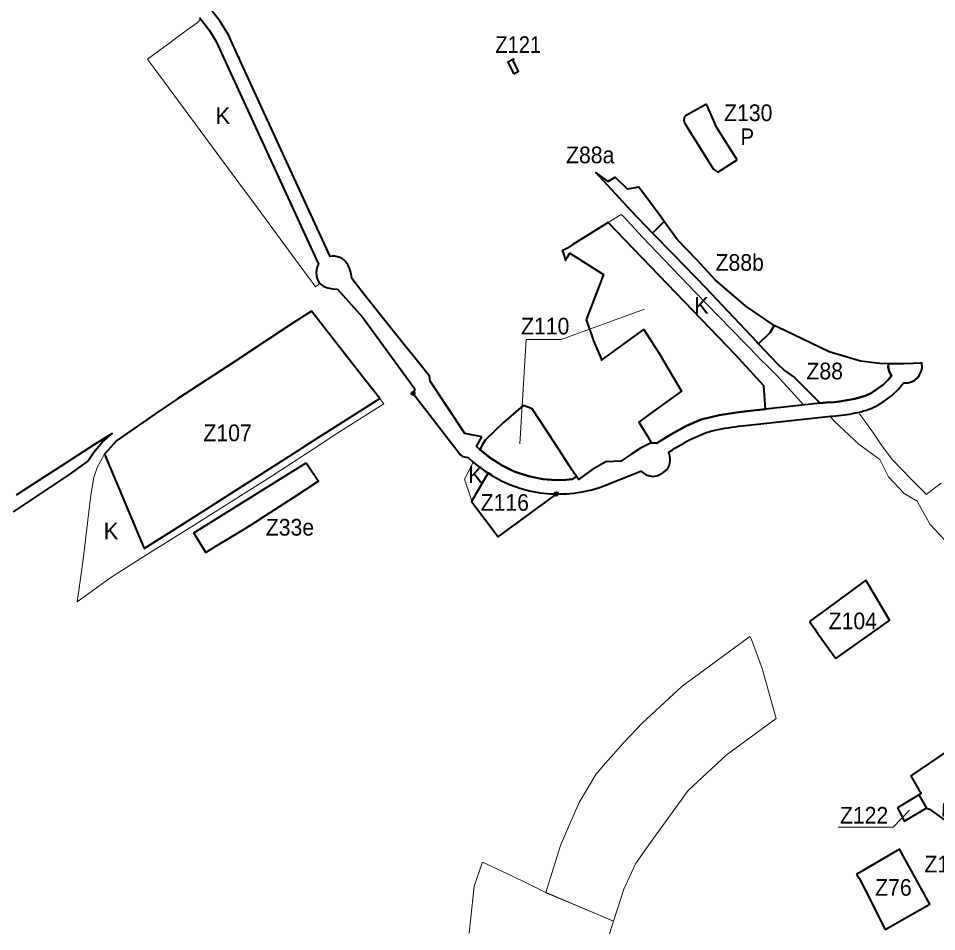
# Model space of a CAD drawing. Extents: x -650276 to -642489, y -1074311 to -1066658.
# Drawn here: x -648043 to -646722, y -1072934 to -1071620 of the extents above; entities that cross this region are included whole.
import ezdxf

# ---------------------------------------------------------------- set-up
doc = ezdxf.new("R2010")
doc.units = 0
doc.header["$LTSCALE"] = 9.6
doc.header["$PDMODE"] = 32
doc.header["$PDSIZE"] = 4.8
for name, color, linetype, lineweight in [('44', 7, 'Continuous', 40), ('45', 7, 'Continuous', 40), ('46', 7, 'Continuous', 13), ('47', 7, 'Continuous', 13), ('48', 7, 'Continuous', 13), ('60', 7, 'Continuous', 35)]:
    doc.layers.add(name, color=color, linetype=linetype, lineweight=lineweight)

msp = doc.modelspace()

# ---------------------------------------------------------------- linework, layer by layer
at = {"layer": '44'}
msp.add_line((-646978.602, -1072088.66), (-646951.95, -1072116.84), dxfattribs=at)
for points in [[(-647725.629, -1071678.373), (-647735.352, -1071657.117), (-647741.34, -1071644.028), (-647753.065, -1071625.201), (-647767.784, -1071606.225), (-647782.408, -1071590.847), (-647798.911, -1071576.526), (-647817.375, -1071563.458), (-647834.953, -1071553.406)], [(-647782.97, -1071619.278), (-647769.498, -1071636.647), (-647758.994, -1071653.513), (-647743.48, -1071687.426), (-647611.514, -1071974.086)], [(-647563.77, -1071994.38), (-647564.751, -1071987.939), (-647566.62, -1071981.3), (-647569.422, -1071974.943), (-647573.283, -1071969.627), (-647575.415, -1071967.709), (-647577.881, -1071965.979), (-647581.036, -1071964.346), (-647584.363, -1071963.196), (-647588.064, -1071962.51), (-647591.518, -1071962.387), (-647594.731, -1071962.714), (-647725.614, -1071678.405), (-647726.774, -1071675.885), (-647725.629, -1071678.373)], [(-647611.514, -1071974.086), (-647613.455, -1071978.031), (-647614.654, -1071982.238), (-647615.083, -1071986.65), (-647614.76, -1071990.762), (-647613.637, -1071995.081), (-647611.779, -1071999.069), (-647609.808, -1072001.962)], [(-647542.57, -1072021.99), (-647558.97, -1072000.62), (-647563.77, -1071994.38)], [(-647609.808, -1072001.962), (-647604.924, -1072005.628), (-647598.384, -1072007.852), (-647591.564, -1072009.255), (-647584.202, -1072009.747)], [(-647584.202, -1072009.747), (-647547.916, -1072050.439), (-647473.022, -1072153.375), (-647475.57, -1072159.74)], [(-647452.23, -1072134.91), (-647472.86, -1072109.13), (-647474.72, -1072106.81), (-647485.6, -1072093.2), (-647504.73, -1072069.29), (-647542.57, -1072021.99)], [(-646790.432, -1072129.195), (-646791.977, -1072122.305), (-646791.84, -1072117.172), (-646804.27, -1072116.98), (-646832.01, -1072113.66), (-646876.83, -1072100.12), (-646941.054, -1072069.172), (-646956.04, -1072061.95), (-646962.041, -1072072.379), (-646978.602, -1072088.66)], [(-646951.95, -1072116.84), (-646941.45, -1072126.84), (-646927.14, -1072136.74), (-646891.05, -1072172.79), (-646890.044, -1072174.056), (-646876.712, -1072172.592), (-646873.495, -1072172.799), (-646862.09, -1072171.444), (-646840.102, -1072167.623), (-646825.169, -1072163.164), (-646816.74, -1072159.571), (-646799, -1072147), (-646792.58, -1072140.847), (-646787.481, -1072134.643), (-646790.432, -1072129.195)], [(-646808.466, -1072177.78), (-646797.713, -1072171.151), (-646787.223, -1072163.402), (-646777.129, -1072153.576), (-646770.057, -1072144.677), (-646763.959, -1072144.535), (-646758.736, -1072143.137), (-646753.929, -1072140.612), (-646750.164, -1072137.467), (-646747.39, -1072134.069), (-646744.554, -1072128.415), (-646743.411, -1072123.612), (-646743.596, -1072115.985), (-646746.547, -1072116.221), (-646756.298, -1072117), (-646769.668, -1072117.517), (-646783.449, -1072117.302), (-646791.84, -1072117.172)], [(-646791.84, -1072117.172), (-646791.977, -1072122.305), (-646790.432, -1072129.195)], [(-647376.68, -1072222.29), (-647401.221, -1072217.342), (-647451.21, -1072142.08), (-647452.23, -1072134.91)], [(-646790.432, -1072129.195), (-646787.481, -1072134.643), (-646792.58, -1072140.847), (-646799, -1072147), (-646816.74, -1072159.571), (-646825.169, -1072163.164), (-646840.102, -1072167.623), (-646862.09, -1072171.444), (-646873.495, -1072172.799), (-646876.712, -1072172.592), (-646890.044, -1072174.056), (-646968.503, -1072182.672)], [(-647475.57, -1072159.74), (-647447.73, -1072195.72), (-647407.34, -1072247.93)], [(-646835.538, -1072187.097), (-646831.517, -1072186.103), (-646827.501, -1072184.997), (-646823.496, -1072183.769), (-646819.509, -1072182.408), (-646815.549, -1072180.906), (-646811.621, -1072179.254), (-646808.466, -1072177.78)], [(-646968.503, -1072182.672), (-646995.137, -1072185.597), (-647010.148, -1072187.308), (-647035.515, -1072191.104), (-647060.973, -1072197.439), (-647082.249, -1072206.591), (-647104.989, -1072219.005), (-647124.81, -1072231.168), (-647133, -1072230.754), (-647148.71, -1072238.76)], [(-647017.46, -1072208.427), (-647012.612, -1072207.773), (-647007.734, -1072207.162), (-647002.826, -1072206.583), (-646997.894, -1072206.024), (-646992.937, -1072205.475), (-646874.517, -1072192.471), (-646871.271, -1072192.675)], [(-646871.271, -1072192.675), (-646867.371, -1072192.234), (-646867.32, -1072192.228), (-646863.448, -1072191.771), (-646859.506, -1072191.276), (-646855.545, -1072190.741), (-646851.567, -1072190.155)], [(-646851.567, -1072190.155), (-646847.575, -1072189.507), (-646843.569, -1072188.789), (-646843.535, -1072188.782), (-646839.556, -1072187.988), (-646835.538, -1072187.097)], [(-648050.276, -1072330.025), (-647969.894, -1072276.479), (-647944.45, -1072258.458), (-647941.77, -1072254.45), (-647934.9, -1072244.55), (-647923.16, -1072229.85), (-647908.5, -1072217.29), (-647933.95, -1072233.18), (-647942.21, -1072238.54), (-648046.69, -1072306.3)], [(-647108.131, -1072244.373), (-647103.164, -1072241.306), (-647098.944, -1072238.718), (-647094.737, -1072236.177), (-647090.531, -1072233.695), (-647086.322, -1072231.285), (-647082.102, -1072228.962), (-647077.867, -1072226.739), (-647073.611, -1072224.631), (-647069.33, -1072222.651), (-647064.868, -1072220.746), (-647054.841, -1072216.479), (-647050.344, -1072215.107), (-647045.786, -1072213.858), (-647041.174, -1072212.723), (-647036.512, -1072211.693), (-647031.807, -1072210.758), (-647027.061, -1072209.91), (-647022.278, -1072209.136), (-647017.46, -1072208.427)], [(-647240.55, -1072279.42), (-647246.206, -1072283.328), (-647255.671, -1072284.192), (-647269.579, -1072284.489), (-647288.769, -1072283.003), (-647309.416, -1072278.875), (-647330.032, -1072271.935), (-647347.382, -1072263.623), (-647363.317, -1072253.632), (-647363.786, -1072253.254), (-647379.422, -1072240.675), (-647384.567, -1072236.256), (-647376.68, -1072222.29)], [(-647148.71, -1072238.76), (-647160.91, -1072246.82), (-647176.7, -1072257.24), (-647198.3, -1072258.09), (-647218.35, -1072269.67), (-647237.6, -1072283.78), (-647240.55, -1072279.42)], [(-647407.34, -1072247.93), (-647404.45, -1072250.66), (-647396.25, -1072252.14), (-647389.072, -1072258.845)], [(-647389.072, -1072258.845), (-647383.813, -1072263.219), (-647372.858, -1072271.363), (-647361.521, -1072278.584), (-647347.369, -1072286.111)], [(-647205.975, -1072294.599), (-647148.171, -1072271.47), (-647139.697, -1072277.484), (-647130.12, -1072279.44), (-647123.774, -1072277.899)], [(-647123.774, -1072277.899), (-647116.323, -1072273.885), (-647109.812, -1072268.588)], [(-647347.369, -1072286.111), (-647335.382, -1072291.341), (-647321.953, -1072296.073), (-647308.157, -1072299.786), (-647292.715, -1072302.646), (-647278.108, -1072304.147), (-647271.395, -1072304.452), (-647269.52, -1072307.17), (-647265.793, -1072304.439)], [(-647265.793, -1072304.439), (-647255.16, -1072304.123), (-647244.428, -1072303.192), (-647232.368, -1072301.4), (-647218.5, -1072298.335), (-647205.975, -1072294.599)]]:
    msp.add_lwpolyline(points, dxfattribs=at)
msp.add_arc((-647130.12, -1072255.012), 24.428, 326.23773, 25.81772, dxfattribs=at)
msp.add_point((-647475.57, -1072159.74), dxfattribs=at)
at = {"layer": '45'}
for points in [[(-647330.34, -1071678.82), (-647339.211, -1071683.431), (-647330.73, -1071700.09)], [(-647330.73, -1071700.09), (-647324.21, -1071696.2), (-647331.65, -1071681.7), (-647330.34, -1071678.82)], [(-647053.43, -1071743.63), (-647083.97, -1071760.74), (-647084.95, -1071761.98), (-647085.71, -1071763.75), (-647086.19, -1071766.95), (-647085.25, -1071770.69), (-647074.99, -1071786.99), (-647073.19, -1071789.9), (-647044.12, -1071836.68)], [(-647009.514, -1071823.81), (-647016.12, -1071813.35), (-647039.14, -1071776.9), (-647044.83, -1071763.37), (-647053.43, -1071743.63)], [(-647044.12, -1071836.68), (-647040.2, -1071839.6), (-647037.23, -1071841.82), (-647009.514, -1071823.81)], [(-647184.81, -1071848.61), (-647185.62, -1071849.12), (-647194.96, -1071854.93), (-647205.62, -1071847.24), (-647212.66, -1071842.15), (-647163.08, -1071896.13), (-647131.146, -1071929.146)], [(-647131.146, -1071929.146), (-647114.479, -1071912.479), (-647118.79, -1071906.59), (-647151.07, -1071863.08), (-647167.15, -1071866.22), (-647184.81, -1071848.61)], [(-646996.8, -1072034.35), (-647040.89, -1071996.58), (-647067.53, -1071967.54), (-647095.51, -1071938.39), (-647114.479, -1071912.479), (-647131.146, -1071929.146), (-647101.07, -1071960.24)], [(-647101.07, -1071960.24), (-647055.16, -1072007.74), (-647023.04, -1072041.63), (-646981.35, -1072085.77), (-646978.602, -1072088.66), (-646962.041, -1072072.379), (-646956.04, -1072061.95), (-646996.8, -1072034.35)], [(-647621.97, -1072041.73), (-647649.76, -1072059.06), (-647683.63, -1072081.94), (-647730.53, -1072112.84), (-647814.58, -1072167.67), (-647845.58, -1072188.94), (-647901.91, -1072227.6), (-647919.68, -1072247.09), (-647862.615, -1072383.084)], [(-647523.71, -1072167.071), (-647545.44, -1072139.35), (-647621.97, -1072041.73)], [(-647862.615, -1072383.084), (-647800.2, -1072343.615), (-647642.504, -1072242.974), (-647616.719, -1072226.154), (-647523.71, -1072167.071)], [(-647362.702, -1072277.035), (-647367.686, -1072273.861), (-647391.761, -1072315.201), (-647353.041, -1072365.971), (-647270.701, -1072305.621), (-647266.974, -1072302.89), (-647272.576, -1072302.903)], [(-646824.42, -1072428.58), (-646878.91, -1072468.54), (-646905.18, -1072487.8)], [(-646824.42, -1072428.58), (-646878.91, -1072468.54), (-646905.18, -1072487.8)], [(-646867.283, -1072540.984), (-646791.569, -1072487.198), (-646790.354, -1072486.136), (-646810.77, -1072451.09), (-646824.42, -1072428.58)], [(-646867.283, -1072540.984), (-646791.569, -1072487.198), (-646790.354, -1072486.136), (-646810.77, -1072451.09), (-646824.42, -1072428.58)], [(-646905.18, -1072487.8), (-646898.1, -1072498.02), (-646893.64, -1072504.45), (-646867.283, -1072540.984)], [(-646905.18, -1072487.8), (-646898.1, -1072498.02), (-646893.64, -1072504.45), (-646867.283, -1072540.984)], [(-646737.05, -1072756.4), (-646732.5, -1072757.63), (-646708.65, -1072775.02), (-646702.45, -1072773.39), (-646712.46, -1072766.76), (-646711.79, -1072750.02), (-646677.39, -1072724.85), (-646660.89, -1072709.97), (-646643.36, -1072746.04), (-646647.93, -1072759.01), (-646612.11, -1072774.56), (-646581.92, -1072723.91), (-646589.37, -1072709.83), (-646605.23, -1072679.37), (-646627.32, -1072636.95), (-646629.86, -1072632.07), (-646648.27, -1072647.48), (-646669.6, -1072654.53), (-646697.89, -1072667.65)], [(-646697.89, -1072667.65), (-646732.95, -1072691.68), (-646759.491, -1072709.878), (-646757.5, -1072713.3), (-646747.87, -1072729.85), (-646744.94, -1072734.88), (-646748.3, -1072737.01), (-646737.05, -1072756.4)]]:
    msp.add_lwpolyline(points, dxfattribs=at)
for points in [[(-647226.41, -1072054.11), (-647219.64, -1072074.29), (-647216.23, -1072084.14), (-647204.78, -1072110.92), (-647204.38, -1072111.87), (-647143.76, -1072067.69), (-647122.33, -1072101.34), (-647089.54, -1072156.53), (-647134.17, -1072188.95), (-647151.05, -1072201.21), (-647138.65, -1072221.5), (-647133, -1072230.754), (-647124.81, -1072231.168), (-647104.989, -1072219.005), (-647082.249, -1072206.591), (-647060.973, -1072197.439), (-647035.515, -1072191.104), (-647010.148, -1072187.308), (-646995.137, -1072185.597), (-646968.503, -1072182.672), (-646971.283, -1072148.82), (-647011.762, -1072104.502), (-647194.903, -1071913.941), (-647238.1, -1071941), (-647245.71, -1071945.77), (-647253.67, -1071950.76), (-647261.12, -1071954.82), (-647259.7, -1071957.06), (-647256.53, -1071968.64), (-647253.85, -1071964.38), (-647249.92, -1071958.12), (-647201.53, -1071988.71)], [(-647226.41, -1072054.11), (-647219.64, -1072074.29), (-647216.23, -1072084.14), (-647204.78, -1072110.92), (-647204.38, -1072111.87), (-647143.76, -1072067.69), (-647122.33, -1072101.34), (-647089.54, -1072156.53), (-647134.17, -1072188.95), (-647151.05, -1072201.21), (-647138.65, -1072221.5), (-647133, -1072230.754), (-647124.81, -1072231.168), (-647104.989, -1072219.005), (-647082.249, -1072206.591), (-647060.973, -1072197.439), (-647035.515, -1072191.104), (-647010.148, -1072187.308), (-646995.137, -1072185.597), (-646968.503, -1072182.672), (-646971.283, -1072148.82), (-647011.762, -1072104.502), (-647194.903, -1071913.941), (-647238.1, -1071941), (-647245.71, -1071945.77), (-647253.67, -1071950.76), (-647261.12, -1071954.82), (-647259.7, -1071957.06), (-647256.53, -1071968.64), (-647253.85, -1071964.38), (-647249.92, -1071958.12), (-647201.53, -1071988.71)], [(-647246.563, -1072270.214), (-647251.85, -1072262.12), (-647271.38, -1072232.23), (-647304.32, -1072181.81), (-647310.33, -1072179.58), (-647317.33, -1072176.99), (-647345.42, -1072201.58), (-647372.1, -1072226.89), (-647375.551, -1072233.387), (-647379.422, -1072240.675), (-647363.317, -1072253.632), (-647347.382, -1072263.623), (-647330.032, -1072271.935), (-647309.416, -1072278.875), (-647288.769, -1072283.003), (-647269.579, -1072284.489), (-647255.671, -1072284.192), (-647246.206, -1072283.328), (-647240.55, -1072279.42)], [(-647246.563, -1072270.214), (-647251.85, -1072262.12), (-647271.38, -1072232.23), (-647304.32, -1072181.81), (-647310.33, -1072179.58), (-647317.33, -1072176.99), (-647345.42, -1072201.58), (-647372.1, -1072226.89), (-647375.551, -1072233.387), (-647379.422, -1072240.675), (-647363.317, -1072253.632), (-647347.382, -1072263.623), (-647330.032, -1072271.935), (-647309.416, -1072278.875), (-647288.769, -1072283.003), (-647269.579, -1072284.489), (-647255.671, -1072284.192), (-647246.206, -1072283.328), (-647240.55, -1072279.42)], [(-647629.67, -1072259.82), (-647611.51, -1072286.26), (-647648.09, -1072309.95), (-647688.26, -1072336.06), (-647702.35, -1072345.14), (-647716.62, -1072353.95), (-647730.97, -1072362.6), (-647745.32, -1072371.26), (-647759.68, -1072379.91), (-647774.04, -1072388.57), (-647791.198, -1072360.119)], [(-646778.2, -1072755.19), (-646755.1, -1072741.28), (-646748.3, -1072737.01), (-646737.05, -1072756.4), (-646768.74, -1072774.78)], [(-646837.81, -1072851.3), (-646836.5, -1072853.76), (-646833.67, -1072857.15), (-646824.89, -1072874.66), (-646796.68, -1072930.92), (-646732.28, -1072894.29), (-646775.85, -1072815.39), (-646834.08, -1072849.15)], [(-646837.81, -1072851.3), (-646836.5, -1072853.76), (-646833.67, -1072857.15), (-646824.89, -1072874.66), (-646796.68, -1072930.92), (-646732.28, -1072894.29), (-646775.85, -1072815.39), (-646834.08, -1072849.15)]]:
    msp.add_lwpolyline(points, close=True, dxfattribs=at)
msp.add_arc((-646767.624, -1072120.384), 24.428, 264.28146, 264.89913, dxfattribs=at)
msp.add_arc((-646767.624, -1072120.384), 24.428, 264.28146, 264.89913, dxfattribs=at)
at = {"layer": '46'}
for points in [[(-647321.863, -1072232.262), (-647313.149, -1072082.081), (-647262.801, -1072082.081), (-647142.741, -1072038.48)], [(-647321.863, -1072232.262), (-647313.149, -1072082.081), (-647262.801, -1072082.081), (-647142.741, -1072038.48)], [(-646864.278, -1072783.783), (-646784.878, -1072783.783), (-646761.687, -1072759.411)]]:
    msp.add_lwpolyline(points, dxfattribs=at)
at = {"layer": '47'}
msp.add_line((-647391.346, -1072314.489), (-647368.024, -1072274.442), dxfattribs=at)
for points in [[(-647817.33, -1071649.51), (-647806.35, -1071641.47), (-647795.76, -1071633.72), (-647794.98, -1071633.15), (-647786.1, -1071626.65), (-647781.134, -1071621.645), (-647769.498, -1071636.647), (-647758.889, -1071653.742), (-647743.48, -1071687.426), (-647611.514, -1071974.086), (-647613.455, -1071978.031), (-647614.654, -1071982.238), (-647615.083, -1071986.65), (-647614.76, -1071990.762), (-647613.637, -1071995.081), (-647611.779, -1071999.069), (-647609.808, -1072001.962), (-647616.12, -1072006.7), (-647621.06, -1072000), (-647644.38, -1071968.3), (-647705.291, -1071885.501), (-647727.85, -1071854.86), (-647857.52, -1071678.92), (-647834.345, -1071661.969), (-647827.42, -1071656.89)], [(-647284.75, -1072877.79), (-647282.31, -1072878.82), (-647192.718, -1072916.582), (-647187.445, -1072918.804), (-647172.48, -1072872.92), (-647155.72, -1072836.46), (-647136.69, -1072808.98), (-647079.74, -1072731.1), (-647025.04, -1072679.96), (-646953.2, -1072627.45), (-646957.5, -1072612.09), (-646973.68, -1072555.68), (-646989.01, -1072513.62), (-646991.24, -1072509.24), (-647063.38, -1072562.42), (-647088.397, -1072580.865), (-647088.4, -1072580.868), (-647146.21, -1072634.02), (-647172.36, -1072661.69), (-647198.77, -1072691.71), (-647212.92, -1072708.05), (-647236.54, -1072748.09), (-647252.29, -1072783.24), (-647263.58, -1072809.97)]]:
    msp.add_lwpolyline(points, close=True, dxfattribs=at)
for points in [[(-646913.373, -1072176.618), (-646931.653, -1072156.802), (-646942.78, -1072144.74), (-646952.48, -1072134.22), (-646964.8, -1072121.83), (-646977.59, -1072108.96), (-646978.45, -1072108.09), (-647036.8, -1072048.41), (-647068.31, -1072015.68), (-647114.59, -1071967.77), (-647145.38, -1071935), (-647173.14, -1071905.45), (-647174.57, -1071904.06), (-647176.32, -1071902.3), (-647194.902, -1071913.942), (-647011.762, -1072104.502)], [(-647011.762, -1072104.502), (-646971.283, -1072148.82), (-646968.503, -1072182.672), (-646913.373, -1072176.618)], [(-647795.4, -1072352.415), (-647679.66, -1072279.15), (-647637.082, -1072251.377), (-647611.306, -1072234.563), (-647589.02, -1072219.66), (-647517.51, -1072174.98), (-647523.71, -1072167.071), (-647616.719, -1072226.154), (-647642.504, -1072242.974), (-647800.888, -1072344.051), (-647810.794, -1072350.315), (-647862.615, -1072383.084), (-647919.68, -1072247.09)], [(-646716.167, -1072288.809), (-646737.449, -1072305.019), (-646738.951, -1072303.49), (-646758.684, -1072283.41), (-646785.958, -1072255.505), (-646800.76, -1072235.668), (-646813.508, -1072217.089), (-646813.516, -1072217.078), (-646832.718, -1072189.697), (-646834.279, -1072186.818), (-646835.199, -1072187.013), (-646835.538, -1072187.097), (-646839.556, -1072187.988), (-646843.535, -1072188.782), (-646843.569, -1072188.789), (-646847.575, -1072189.507), (-646851.567, -1072190.155), (-646855.545, -1072190.741), (-646859.506, -1072191.276), (-646863.448, -1072191.771), (-646867.32, -1072192.228), (-646867.371, -1072192.234), (-646871.271, -1072192.675), (-646873.131, -1072192.558), (-646875.509, -1072192.58), (-646870.21, -1072199.51), (-646833.75, -1072233.32), (-646803.98, -1072254.74), (-646791.59, -1072279.78), (-646769.24, -1072303.65), (-646750.58, -1072315.02), (-646750.12, -1072315.82), (-646742.32, -1072329.62), (-646731.82, -1072348.2), (-646696.83, -1072385.81)], [(-647919.68, -1072247.09), (-647930.36, -1072266.38), (-647934.86, -1072280.99), (-647939.26, -1072306.1), (-647942.54, -1072333.82), (-647950.2, -1072398.61), (-647956.786, -1072446.511)], [(-647389.072, -1072258.845), (-647391.3, -1072263.04), (-647401.88, -1072283.4), (-647391.346, -1072314.489)], [(-647368.024, -1072274.442), (-647372.858, -1072271.363), (-647372.858, -1072271.363), (-647383.813, -1072263.219), (-647389.072, -1072258.845)], [(-647956.786, -1072446.511), (-647958.82, -1072459.74), (-647910.27, -1072424.51), (-647857.52, -1072391.14), (-647795.4, -1072352.415)], [(-647192.93, -1072936.82), (-647187.445, -1072918.804), (-647293.317, -1072873.549), (-647293.351, -1072873.533), (-647331.82, -1072854.49), (-647375.92, -1072833.99), (-647387.64, -1072868.69), (-647392.96, -1072918.277), (-647394.87, -1072936.08)]]:
    msp.add_lwpolyline(points, dxfattribs=at)

# ---------------------------------------------------------------- texts
at = {"layer": '44', "width": 0.95}
msp.add_text('Z88', height=24, dxfattribs=at).set_placement((-646909.741, -1072139.634))
msp.add_text('Z88', height=24, dxfattribs=at).set_placement((-646909.741, -1072139.634))
at = {"layer": '46'}
for s, width, p in [('Z121', 0.9, (-647357.291, -1071670.187)), ('Z130', 0.95, (-647028.202, -1071768.178)), ('Z88a', 0.95, (-647255.564, -1071828.861)), ('Z88b', 0.95, (-647040.507, -1071983.505)), ('Z110', 0.95, (-647320.328, -1072074.974)), ('Z110', 0.95, (-647320.328, -1072074.974)), ('Z107', 0.95, (-647777.22, -1072228.544)), ('Z116', 0.95, (-647378.432, -1072328.636)), ('Z33e', 0.95, (-647687.519, -1072364.366)), ('Z104', 0.95, (-646877.745, -1072499.058)), ('Z104', 0.95, (-646877.745, -1072499.058)), ('Z122', 0.95, (-646861.605, -1072778.534)), ('Z126', 0.95, (-646740.041, -1072848.718)), ('Z76', 0.95, (-646810.899, -1072882.315)), ('Z76', 0.95, (-646810.899, -1072882.315))]:
    msp.add_text(s, height=24, dxfattribs=dict(at, width=width)).set_placement(p)
at = {"layer": '48'}
for p in [(-647759.879, -1071772.452), (-647759.879, -1071772.452), (-647071.498, -1072045.307), (-647396.507, -1072288.9), (-647920.872, -1072369.761)]:
    msp.add_text('K', height=24, dxfattribs=at).set_placement(p)
at = {"layer": '60', "width": 0.9}
msp.add_text('P', height=24, dxfattribs=at).set_placement((-647004.438, -1071802.773))

doc.saveas('drawing.dxf')
